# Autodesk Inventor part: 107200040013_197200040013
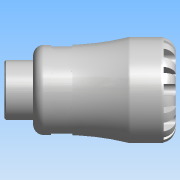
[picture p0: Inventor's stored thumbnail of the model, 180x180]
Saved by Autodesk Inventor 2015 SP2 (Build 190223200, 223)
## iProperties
Created: 2016-12
Part Number: 107200040013_197200040013
Material: PVC-Piping
Description: PLASSON MALE INTEGRAL BRASS THREAD 40X1.1/4" SERIES 1
Document SubType Name: Modeling
Designer: KIM
Mass: 61.7504 g
Surface Area: 140.097 cm^2
Volume: 44.1074 cm^3
Density: 1.4 g/cm^3
Appearance: Smooth - White
Author: KIM
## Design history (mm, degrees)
derived "1072.ipt"
feature "Solid1::1072.ipt"
tag "TaggingFeature1"
body "Solid1"
other parameters: "d0" = 113, "d1" = 30.66, "d6" = 73, "d8" = 59.5, "d13" = 8, "d14" = 8, "d15" = 0, "d17" = 360 deg, "d19" = 8 deg, "d20" = 0.8, "d21" = 0.8, "d22" = 8 deg, "d24" = 0, "d26" = 360 deg, "d32" = 7, "d33" = 7, "d34" = 39.592, "d38" = 19, "d39" = 1.18776, "d42" = 14, "d43" = 9.2, "d45" = 15.68, "d46" = 0, "d59" = 360 deg, "d61" = 11.9, "d62" = 0.8, "d64" = 0, "d65" = 0.7, "d68" = 5.71429, "H_" = 113, "l_" = 73, "R_" = 39.592, "l_2" = 19, "d9" = 10
